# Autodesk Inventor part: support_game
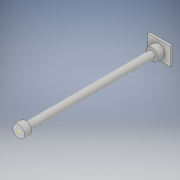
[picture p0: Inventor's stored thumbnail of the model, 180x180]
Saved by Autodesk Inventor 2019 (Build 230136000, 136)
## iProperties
Created: 2020-02
Part Number: support_game
Material: Generic
Document SubType Name: Modeling
Designer: Siddharth
Density: 1 g/cm^3
Appearance: Default
Author: Siddharth
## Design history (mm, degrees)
sketch "Sketch1"
  geometry: C1 r 15 at (0, 0); 1 further point
  constraints: 1 centre point, 1 coincident
  dimensions: "d0" = 30 diameter of C1
extrude "Extrusion1" new body sketch "Sketch1" distance "d1" = 609.6; taper "d2" = 0 deg
sketch "Sketch2"
  geometry: 1 further point
sketch "Sketch3"
  geometry: C1 r 15 at (0, 0) reference; C2 r 25.981 at (0, 0); 1 further point
  constraints: 1 centre point, 1 coincident
extrude "Extrusion2" join sketch "Sketch3" distance "d3" = 30; taper "d4" = 0 deg
sketch "Sketch5"
  geometry: C1 r 15 at (0, 0) reference; C2 r 15 at (0, 0); C3 r 25.981 at (0, 0); 1 further point
  constraints: 2 centre point, 2 coincident
extrude "Extrusion4" join sketch "Sketch5" distance "d7" = 30; taper "d8" = 0 deg
sketch "Sketch6"
  geometry: L1 (-49.845, 39.596)-(49.845, 39.596) reference; L2 (-49.845, -37.733)-(-49.845, 39.596) reference; L3 (49.845, 39.596)-(-49.845, 39.596); L4 (-49.845, 39.596)-(-49.845, -37.733); L5 (-49.845, -37.733)-(49.845, -37.733); L6 (49.845, -37.733)-(49.845, 39.596); 1 further point
  constraints: 8 end point, 2 parallel, 1 horizontal, 1 perpendicular
extrude "Extrusion5" join sketch "Sketch6" distance "d9" = 10; taper "d10" = 0 deg
body "Solid1"
